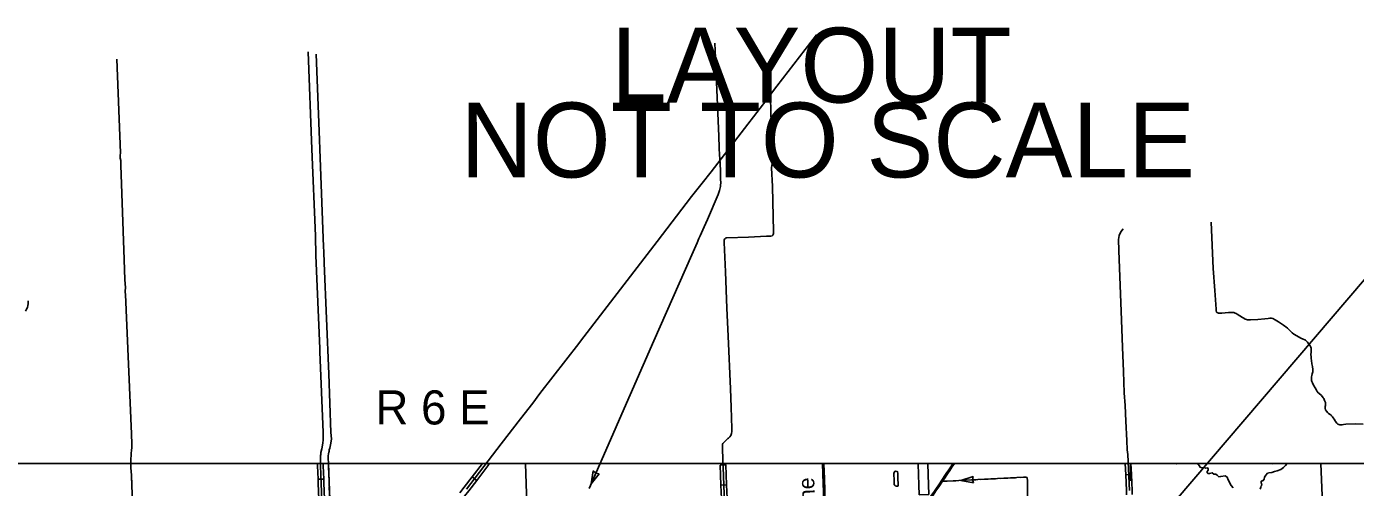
# Model space of a CAD drawing. Extents: x -5566 to 1759129, y -3726 to 731467.
# Drawn here: x -4880.9 to -4614.7, y 507.2 to 599.5 of the extents above; entities that cross this region are included whole.
import ezdxf

# ---------------------------------------------------------------- set-up
doc = ezdxf.new("R2010")
doc.units = 0
doc.layers.add('Default', color=7, linetype='Continuous')
doc.layers.add('R_No Plot', color=7, linetype='Continuous')

msp = doc.modelspace()

# ---------------------------------------------------------------- linework, layer by layer
at = {"layer": 'Default'}
for p, q in [((-4788.58, 511.98), (-4788.3, 511.77)), ((-4740.83, 511.7), (-4741.97, 511.66)), ((-4659.8, 511.95), (-4659.81, 508.55)), ((-4821.39, 508.86), (-4822.53, 508.82)), ((-4791.65, 509.29), (-4790.75, 508.6)), ((-4767.84, 507.92), (-4767.44, 510.5)), ((-4767.84, 507.92), (-4766.2, 509.95)), ((-4767.44, 510.5), (-4766.9, 510.06)), ((-4766.2, 509.95), (-4766.89, 510.06)), ((-4693.79, 508.59), (-4691.31, 509.38)), ((-4693.79, 508.59), (-4691.23, 508.11)), ((-4691.31, 509.38), (-4691.45, 508.7)), ((-4691.23, 508.11), (-4691.45, 508.7)), ((-4659.58, 509.79), (-4660.72, 509.73)), ((-4740.68, 507.7), (-4741.82, 507.66))]:
    msp.add_line(p, q, dxfattribs=at)
for points in [[(-4722.68, 597.88), (-4730.63, 587.57), (-4731.88, 585.91), (-4732.18, 585.53), (-4737.13, 579.1), (-4743.81, 570.42), (-4745.6, 568.17), (-4747.71, 565.46), (-4754.62, 556.44), (-4769.95, 536.49), (-4770.28, 536.05), (-4778.1, 526.03), (-4779.51, 524.1), (-4781.98, 520.93), (-4785.83, 515.93), (-4792.8, 506.87)], [(-4820.65, 472.78), (-4820.71, 475.23), (-4821.35, 493.95), (-4821.93, 508.07), (-4822.06, 511.53), (-4822.06, 512.62), (-4822.03, 513.56), (-4822, 513.82), (-4821.97, 514.21), (-4821.8, 514.93), (-4821.58, 516.04), (-4821.5, 516.72), (-4821.48, 517.29), (-4821.49, 518.21), (-4822.18, 534.35), (-4822.2, 535.05), (-4822.95, 553.69), (-4823.07, 557.61), (-4823.78, 574.98), (-4824.52, 594.47)], [(-4822.88, 593.97), (-4822.25, 576.85), (-4822.15, 574.98), (-4821.41, 555.42), (-4821.35, 554.46), (-4821.28, 552.11), (-4820.36, 529.93), (-4819.95, 518.23), (-4819.86, 516.91), (-4819.96, 516.05), (-4820.05, 515.7), (-4820.1, 515.39), (-4820.2, 515.09), (-4820.27, 514.75), (-4820.33, 514.42), (-4820.34, 514.29), (-4820.44, 513.91), (-4820.49, 513.54), (-4820.5, 513.04), (-4820.46, 512.01), (-4818.96, 472.49)], [(-4743.04, 596.2), (-4742.97, 594.75), (-4742.63, 586.87), (-4742.24, 577.57), (-4742.18, 575.23), (-4742.12, 573.74), (-4742.06, 573.19), (-4742.02, 572.82), (-4741.96, 572.28), (-4741.91, 570.33)], [(-4862.86, 593), (-4862.11, 574.2), (-4862.16, 573.69), (-4862.16, 573.18), (-4862.07, 572.68), (-4862.07, 571.74), (-4861.38, 552.84), (-4861.21, 548.82), (-4861.13, 547.25), (-4861.13, 547.06), (-4861.19, 546.74), (-4861.19, 546.59), (-4861.18, 546.43), (-4861.14, 546.29), (-4861.09, 545.87), (-4860.14, 524.13), (-4859.93, 517.93), (-4859.83, 515.84), (-4859.85, 515.28), (-4859.93, 514.5), (-4859.95, 514.16), (-4859.96, 513.8), (-4860.05, 512.75), (-4860.02, 512.07), (-4860.02, 511.11), (-4859.93, 509.67), (-4858.75, 476.57)], [(-4740.26, 480.92), (-4741.51, 514.81), (-4741.5, 515.57), (-4741.49, 515.88), (-4741.43, 516.01), (-4741.32, 516.14), (-4741.19, 516.27), (-4740.41, 516.98), (-4740.33, 517.05), (-4740.05, 517.3), (-4739.84, 517.58), (-4739.75, 517.8), (-4739.7, 518), (-4739.65, 518.4), (-4739.64, 519.03), (-4739.77, 523.29), (-4739.92, 526.98), (-4740.39, 537.47), (-4740.67, 543.13), (-4740.94, 550.42), (-4741.19, 556.29), (-4741.2, 556.64), (-4741.15, 556.83), (-4741.06, 557), (-4740.94, 557.13), (-4740.84, 557.17), (-4740.61, 557.22), (-4736.28, 557.36), (-4732.68, 557.52), (-4732.04, 557.54), (-4731.81, 557.55), (-4731.59, 557.63), (-4731.42, 557.75), (-4731.33, 557.9), (-4731.29, 558.05), (-4731.27, 558.45), (-4731.49, 567.5), (-4731.69, 571.2), (-4731.59, 572.07), (-4731.7, 577.61), (-4731.8, 582.58), (-4731.86, 585.28), (-4731.88, 585.44), (-4731.89, 585.7), (-4731.88, 585.91)], [(-4813.76, 313.86), (-4581.46, 585.64), (-4581.46, 585.64)], [(-4741.91, 570.33), (-4741.91, 569.1), (-4741.88, 568.83), (-4741.85, 568.33), (-4741.92, 567.61), (-4741.92, 567.47), (-4741.99, 567.21), (-4742.14, 566.67), (-4742.38, 565.91), (-4744.54, 560.88), (-4745.2, 559.4), (-4745.96, 557.63), (-4746.25, 557.05), (-4746.57, 556.21), (-4747.65, 553.78), (-4755.26, 536.54), (-4762.14, 520.87), (-4763.47, 517.83), (-4768.25, 506.99)], [(-4643.61, 560.36), (-4643.19, 551.07), (-4642.85, 546.62), (-4642.64, 542.89), (-4642.61, 542.56), (-4642.53, 542.33), (-4642.44, 542.21), (-4642.29, 542.15), (-4642.12, 542.11), (-4641.76, 542.09), (-4641.45, 542.12), (-4640.16, 542.21), (-4639.45, 542.25), (-4639.06, 542.21), (-4638.82, 542.13), (-4638.64, 542.03), (-4638.43, 541.92), (-4637.36, 541.25), (-4637.06, 541.08), (-4636.83, 540.93), (-4636.56, 540.84), (-4636.35, 540.8), (-4636.14, 540.77), (-4635.75, 540.76), (-4634.29, 540.83), (-4632.85, 540.96), (-4632.21, 541.03), (-4631.89, 541.08), (-4631.52, 541.1), (-4631.24, 541.03), (-4630.78, 540.79), (-4630.16, 540.38), (-4629.91, 540.22), (-4629.5, 539.96), (-4629.14, 539.71), (-4628.88, 539.53), (-4628.64, 539.34), (-4628.31, 539.07), (-4627.7, 538.48), (-4627.37, 538.15), (-4627.04, 537.88), (-4626.45, 537.55), (-4625.67, 537.13), (-4625.18, 536.9), (-4624.84, 536.74), (-4624.7, 536.67), (-4624.56, 536.56), (-4624.35, 536.31), (-4623.98, 535.83), (-4623.76, 535.54), (-4623.65, 535.28), (-4623.61, 535.07), (-4623.59, 534.69), (-4623.59, 534.38), (-4623.62, 533.74), (-4623.59, 533.46), (-4623.56, 533.04), (-4623.52, 532.62), (-4623.43, 531.99), (-4623.34, 531.39), (-4623.27, 530.81), (-4623.28, 530.35), (-4623.35, 529.97), (-4623.43, 529.6), (-4623.5, 529.32), (-4623.52, 528.93), (-4623.51, 528.64), (-4623.43, 528.43), (-4623.32, 528.15), (-4623.14, 527.71), (-4622.78, 527.14), (-4622.54, 526.71), (-4622.36, 526.41), (-4622.19, 526.18), (-4622.07, 526.06), (-4621.53, 525.63), (-4621.16, 525.14), (-4621.04, 524.99), (-4620.89, 524.64), (-4620.72, 524.24), (-4620.7, 524.06), (-4620.73, 523.64), (-4620.75, 523.42), (-4620.79, 523.19), (-4620.76, 522.98), (-4620.71, 522.74), (-4620.51, 522.49), (-4620.45, 522.41), (-4620.28, 522.22), (-4620.09, 522.04), (-4619.78, 521.81), (-4619.6, 521.66), (-4619.5, 521.53), (-4619.32, 521.34), (-4619.16, 521.17), (-4618.95, 520.84), (-4618.8, 520.53), (-4618.7, 520.38), (-4618.44, 520.06), (-4618.22, 519.9), (-4618.01, 519.81)], [(-4660, 506.58), (-4660.34, 513.79), (-4660.42, 514.7), (-4660.48, 516.58), (-4660.73, 520.44), (-4660.85, 523.64), (-4661.04, 526.13), (-4661.19, 530.44), (-4661.41, 535.3), (-4661.61, 540.73), (-4662.12, 554.66), (-4662.2, 556.86), (-4662.02, 557.68), (-4661.71, 558.42), (-4661.25, 559.01)], [(-4880.57, 544.59), (-4880.59, 543.98), (-4880.66, 543.65), (-4880.74, 543.23), (-4880.91, 542.94), (-4881.14, 542.54)], [(-4618.01, 519.81), (-4617.81, 519.75), (-4617.4, 519.76), (-4617.08, 519.77), (-4616.62, 519.84), (-4614.75, 519.94), (-4613.15, 519.89)], [(-4860.02, 511.98), (-4860.02, 511.98), (-4860.02, 511.98), (-4860.02, 511.98), (-4860.02, 511.98), (-4860.02, 511.39)], [(-4822.53, 508.82), (-4822.63, 511.52), (-4822.63, 511.96), (-4822.63, 511.96)], [(-4821.39, 508.86), (-4821.49, 511.54), (-4821.49, 511.96), (-4821.49, 511.96)], [(-4820.44, 511.4), (-4820.33, 508.4)], [(-4789.58, 511.98), (-4791.65, 509.29)], [(-4788.3, 511.77), (-4790.75, 508.6)], [(-4788.15, 511.98), (-4788.3, 511.77)], [(-4779.94, 480.72), (-4780.01, 484.03), (-4780.95, 511.91)], [(-4741.82, 507.66), (-4741.97, 511.66)], [(-4741.97, 511.66), (-4741.97, 511.66), (-4741.97, 511.66), (-4741.97, 511.66)], [(-4740.68, 507.7), (-4740.83, 511.7)], [(-4740.83, 511.7), (-4740.83, 511.7), (-4740.83, 511.59), (-4740.83, 511.7)], [(-4721.5, 512), (-4721.44, 509.85), (-4721.21, 504.44), (-4721.19, 503.58), (-4721.06, 500.92), (-4721.02, 499.41), (-4721, 498.31), (-4720.92, 497.15), (-4720.97, 496.33), (-4720.83, 494.79), (-4720.83, 493.7), (-4720.81, 492.67), (-4720.79, 492.03), (-4720.74, 490.87), (-4720.68, 489.55), (-4720.61, 487.86), (-4720.65, 487.02), (-4720.61, 486.4), (-4720.54, 485.14), (-4720.56, 484.63), (-4720.37, 481.5), (-4720.32, 479.12), (-4720.18, 477.16), (-4720.18, 477.1)], [(-4721.19, 511.9), (-4721.07, 508.91), (-4720.92, 504.38), (-4720.83, 502.35), (-4720.73, 499.42), (-4720.68, 497.42), (-4720.57, 495.13), (-4720.48, 493.22), (-4720.44, 491.14), (-4720.38, 489.71), (-4720.33, 488.95), (-4720.33, 488.17), (-4720.24, 486.53), (-4720.18, 485.02), (-4720.16, 483.57), (-4720.1, 482.37), (-4720.01, 480.49), (-4719.92, 479.34), (-4719.88, 477.99), (-4719.86, 477.6)], [(-4702.08, 505.69), (-4702.17, 507.66), (-4702.28, 511.9), (-4702.28, 511.9)], [(-4700.38, 511.94), (-4700.38, 511.94), (-4700.27, 507.72), (-4700.18, 505.78), (-4702.08, 505.69)], [(-4695.33, 511.98), (-4695.63, 511.51), (-4696.15, 510.75), (-4696.69, 509.99), (-4696.96, 509.57), (-4697.56, 508.67), (-4698.2, 507.72), (-4698.65, 507.06), (-4699.07, 506.48), (-4699.63, 505.62), (-4700.14, 504.93)], [(-4700.11, 504.44), (-4699.73, 505.04), (-4699.29, 505.62), (-4698.76, 506.5), (-4698.01, 507.53), (-4697.43, 508.47), (-4697.25, 508.73), (-4696.93, 509.19), (-4696.71, 509.54), (-4696.43, 509.95), (-4695.97, 510.61), (-4695.55, 511.24), (-4695.03, 511.98)], [(-4660.72, 509.73), (-4660.82, 511.98)], [(-4659.58, 509.79), (-4659.68, 511.98)], [(-4650.62, 511.98), (-4650.48, 511.94), (-4650.08, 511.98)], [(-4646.55, 511.98), (-4646.25, 511.83), (-4646.04, 511.58), (-4645.81, 511.23), (-4645.5, 511.11), (-4645.15, 511.18), (-4644.93, 511.2), (-4644.73, 511.08), (-4644.34, 511.1), (-4644.24, 510.95), (-4644.24, 510.67), (-4644.42, 510.4), (-4644.41, 510.15), (-4644.2, 509.97), (-4643.92, 509.96), (-4643.65, 510.05), (-4643.4, 510.1), (-4643.1, 509.87), (-4642.7, 509.82), (-4642.42, 509.66), (-4642.1, 509.32), (-4641.71, 509.39), (-4640.8, 509.54), (-4640.41, 509.27), (-4640.23, 508.71), (-4640.01, 508.41), (-4639.86, 508.02), (-4639.59, 507.6), (-4639.24, 507.12)], [(-4628.4, 511.98), (-4628.75, 511.62), (-4629.14, 511.19), (-4629.68, 510.79), (-4630.39, 510.53), (-4630.95, 510.39), (-4631.45, 510.21), (-4632.03, 510.13), (-4632.32, 510.03), (-4632.68, 509.65), (-4632.9, 509.27), (-4633, 508.83), (-4633.26, 508.53), (-4633.43, 508.53), (-4633.57, 508.42), (-4633.63, 508.14), (-4633.54, 507.98), (-4633.49, 507.65), (-4633.62, 507.51), (-4633.68, 507.22), (-4633.79, 506.87)], [(-4631.02, 511.98), (-4631.26, 511.94), (-4631.92, 511.96), (-4632.05, 511.98)], [(-4621.63, 512), (-4620.32, 479.61)], [(-4859.97, 510.39), (-4859.93, 509.67), (-4859.85, 507.39)], [(-4822.37, 504.81), (-4822.5, 508.05), (-4822.53, 508.82)], [(-4821.23, 504.86), (-4821.36, 508.1), (-4821.39, 508.86)], [(-4791.65, 509.29), (-4793.25, 507.22), (-4794.1, 506.12)], [(-4790.75, 508.6), (-4792.35, 506.52), (-4793.2, 505.42)], [(-4766.62, 510.67), (-4767.84, 507.92)], [(-4707.14, 508.54), (-4707.21, 510.01), (-4707.14, 510.17), (-4707.01, 510.37), (-4706.87, 510.44), (-4706.59, 510.42), (-4706.44, 510.35), (-4706.4, 510.06), (-4706.4, 508.98)], [(-4706.4, 508.98), (-4706.34, 507.85), (-4706.34, 507.6), (-4706.34, 507.5), (-4706.47, 507.45), (-4706.65, 507.45), (-4706.8, 507.47), (-4706.92, 507.58), (-4707.09, 507.72), (-4707.09, 507.76), (-4707.13, 507.94), (-4707.14, 508.54)], [(-4680.39, 502.07), (-4680.42, 508.6), (-4680.46, 509.07), (-4680.54, 509.2), (-4680.77, 509.23), (-4681.18, 509.23), (-4692.95, 508.63), (-4696.51, 508.43), (-4697.43, 508.47)], [(-4694.79, 508.53), (-4696.51, 508.43), (-4697.43, 508.47)], [(-4690.79, 508.74), (-4692.95, 508.63), (-4693.79, 508.59)], [(-4686.79, 508.95), (-4689.79, 508.79)], [(-4682.78, 509.15), (-4685.79, 509)], [(-4680.42, 507.46), (-4680.42, 508.6), (-4680.46, 509.07), (-4680.54, 509.2), (-4680.77, 509.23), (-4681.18, 509.23), (-4681.78, 509.2)], [(-4660.55, 505.74), (-4660.56, 506.56), (-4660.72, 509.73)], [(-4659.41, 505.76), (-4659.43, 506.6), (-4659.58, 509.79)], [(-4820.29, 507.39), (-4820.17, 504.39)], [(-4741.67, 503.65), (-4741.82, 507.66)], [(-4740.53, 503.69), (-4740.68, 507.7)]]:
    msp.add_lwpolyline(points, dxfattribs=at)
at = {"layer": 'R_No Plot'}
msp.add_lwpolyline([(-5018.99, 168.24), (-5018.99, 511.98), (-4446.6, 511.98), (-4446.6, 160.5), (-4913.43, 160.5)], dxfattribs=at)

# ---------------------------------------------------------------- texts
at = {"layer": 'Default'}
for s, height, p in [('LAYOUT', 15, (-4763.82, 584.3)), ('NOT TO SCALE', 15, (-4794, 569.3)), ('R 6 E', 6.835, (-4811.03, 519.81))]:
    msp.add_text(s, height=height, dxfattribs=at).set_placement(p)
msp.add_text('Cache', height=3.205, rotation=92.0111, dxfattribs=at).set_placement((-4722.72, 496.87))

doc.saveas('drawing.dxf')
